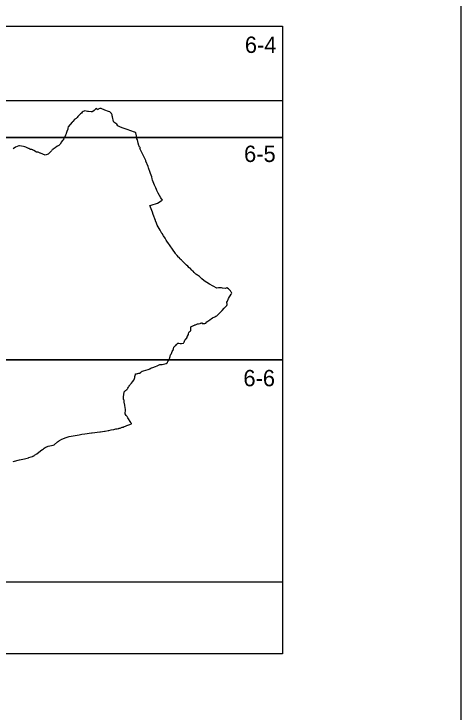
# Model space of a CAD drawing. Extents: x -449577 to -436680, y -1132317 to -1125726.
# Drawn here: x -443787.2 to -443535.8, y -1131954.1 to -1131561.7 of the extents above; entities that cross this region are included whole.
import ezdxf

# ---------------------------------------------------------------- set-up
doc = ezdxf.new("R2010")
doc.units = 0
for name, color, linetype in [('Vrstva 1', 7, 'Continuous'), ('Vrstva 10', 7, 'Continuous'), ('Vrstva 4', 7, 'Continuous')]:
    doc.layers.add(name, color=color, linetype=linetype)

msp = doc.modelspace()

# ---------------------------------------------------------------- linework, layer by layer
at = {"layer": 'Vrstva 1'}
msp.add_lwpolyline([(-445020.82, -1131267.17), (-445020.82, -1132317.17), (-443535.82, -1132317.17), (-443535.82, -1131267.17)], close=True, dxfattribs=at)
msp.add_lwpolyline([(-443787.53, -1131813.29), (-443783.99, -1131812.42), (-443781.22, -1131811.75), (-443780.55, -1131811.54), (-443779.06, -1131811.18), (-443778.85, -1131811.12), (-443777.42, -1131810.73), (-443776.82, -1131810.47), (-443776.6, -1131810.37), (-443776.44, -1131810.31), (-443775.62, -1131809.86), (-443775.56, -1131809.82), (-443774.25, -1131809.04), (-443773.1, -1131807.99), (-443772.45, -1131807.49), (-443772.32, -1131807.38), (-443772.3, -1131807.37), (-443772.14, -1131807.24), (-443771.99, -1131807.14), (-443771.19, -1131806.58), (-443771.13, -1131806.54), (-443771.06, -1131806.49), (-443770.55, -1131806.14), (-443770.18, -1131805.88), (-443769.52, -1131805.42), (-443768.93, -1131805.01), (-443768.77, -1131805.04), (-443768.76, -1131805.04), (-443768.74, -1131805.02), (-443768.01, -1131804.63), (-443765.05, -1131804.05), (-443764.63, -1131803.9), (-443762.6, -1131802.27), (-443762.13, -1131801.93), (-443762.1, -1131801.91), (-443761.74, -1131801.65), (-443761.56, -1131801.53), (-443760.17, -1131800.83), (-443758.76, -1131800.19), (-443758.46, -1131800.04), (-443757.2, -1131799.58), (-443756.2, -1131799.33), (-443750.49, -1131798.27), (-443749.07, -1131798.01), (-443747.36, -1131797.76), (-443743.49, -1131797.19), (-443743.25, -1131797.16), (-443738.95, -1131796.64), (-443738.42, -1131796.58), (-443736.27, -1131796.22), (-443735.95, -1131796.17), (-443734.29, -1131795.9), (-443733.89, -1131795.83), (-443732.48, -1131795.54), (-443731.19, -1131795.27), (-443730.98, -1131795.23), (-443729.81, -1131795), (-443729.14, -1131794.87), (-443729.12, -1131794.87), (-443728.21, -1131794.66), (-443728.14, -1131794.64), (-443727.49, -1131794.48), (-443727.14, -1131794.37), (-443726.25, -1131794.08), (-443725.81, -1131793.93), (-443725.16, -1131793.69), (-443725.04, -1131793.65), (-443723.95, -1131793.16), (-443723.95, -1131793.16), (-443723.83, -1131793.12), (-443723.18, -1131792.89), (-443723.09, -1131792.86), (-443722.66, -1131792.7), (-443721, -1131792.12), (-443721.02, -1131792.07), (-443721.13, -1131791.9), (-443721.29, -1131791.67), (-443721.51, -1131791.35), (-443723.21, -1131788.71), (-443723.42, -1131788.36), (-443723.59, -1131788.09), (-443724.03, -1131787.38), (-443724.56, -1131786.53), (-443724.4, -1131784.17), (-443724.39, -1131784.08), (-443724.78, -1131781.78), (-443724.78, -1131781.76), (-443724.79, -1131781.74), (-443724.79, -1131781.74), (-443724.79, -1131781.71), (-443725.2, -1131779.88), (-443725.21, -1131779.69), (-443725.27, -1131778.89), (-443725.37, -1131778.61), (-443725.38, -1131778.59), (-443725.49, -1131778.37), (-443725.53, -1131778.29), (-443725.54, -1131777.91), (-443725.57, -1131777.21), (-443725.52, -1131776.72), (-443725.52, -1131776.7), (-443725.43, -1131775.84), (-443725.41, -1131775.73), (-443725.12, -1131774.09), (-443725.04, -1131774.01), (-443724.74, -1131773.67), (-443724.68, -1131773.6), (-443724.42, -1131773.48), (-443724.36, -1131773.42), (-443724.1, -1131773.22), (-443723.87, -1131773.04), (-443723.66, -1131772.88), (-443723.6, -1131772.84), (-443723.52, -1131772.71), (-443723.44, -1131772.59), (-443723.33, -1131772.42), (-443723.11, -1131772.09), (-443722.69, -1131771.44), (-443722.56, -1131771.19), (-443722.55, -1131771.18), (-443722.41, -1131770.89), (-443722.36, -1131770.8), (-443722.18, -1131770.47), (-443722.04, -1131770.32), (-443721.74, -1131770.01), (-443721.57, -1131769.83), (-443721.29, -1131769.48), (-443721.16, -1131769.31), (-443720.47, -1131768.46), (-443719.81, -1131767.65), (-443719.52, -1131767.29), (-443719.28, -1131766.12), (-443719.22, -1131765.89), (-443719.15, -1131765.61), (-443718.83, -1131764.3), (-443718.75, -1131764.02), (-443718.75, -1131763.99), (-443718.73, -1131763.94), (-443718.57, -1131763.93), (-443718.55, -1131763.93), (-443718.31, -1131763.93), (-443717.62, -1131763.91), (-443717.61, -1131763.91), (-443717.58, -1131763.91), (-443716.9, -1131763.73), (-443716.7, -1131763.67), (-443716.28, -1131763.56), (-443716.26, -1131763.55), (-443716.2, -1131763.49), (-443715.9, -1131763.21), (-443715.78, -1131763.13), (-443715.44, -1131762.87), (-443715.02, -1131762.55), (-443714.95, -1131762.53), (-443714.39, -1131762.37), (-443711.69, -1131761.61), (-443711.1, -1131761.34), (-443710.77, -1131761.18), (-443710.72, -1131761.16), (-443710.62, -1131761.11), (-443710.26, -1131760.93), (-443710.21, -1131760.91), (-443710.18, -1131760.89), (-443710.17, -1131760.89), (-443710.14, -1131760.87), (-443709.83, -1131760.72), (-443709.77, -1131760.68), (-443709.66, -1131760.63), (-443708.58, -1131760.3), (-443708.15, -1131760.12), (-443707.63, -1131759.9), (-443706.62, -1131759.49), (-443705.2, -1131758.86), (-443705.06, -1131758.85), (-443703.93, -1131758.8), (-443701.53, -1131758.24), (-443701, -1131757.84), (-443700.93, -1131757.72), (-443700.84, -1131757.54), (-443700.58, -1131757.03), (-443700.23, -1131756.6), (-443700.21, -1131756.57), (-443700, -1131756.28), (-443699.89, -1131756.12), (-443699.88, -1131756.11), (-443699.34, -1131754.33), (-443699.33, -1131754.3), (-443699.13, -1131753.35), (-443698.87, -1131752.89), (-443698.68, -1131752.56), (-443698.13, -1131751.44), (-443697.75, -1131750.93), (-443697.72, -1131750.8), (-443697.65, -1131750.5), (-443697.62, -1131750.36), (-443697.56, -1131750.11), (-443697.54, -1131750.01), (-443697.22, -1131749), (-443697.21, -1131748.99), (-443696.92, -1131748.71), (-443696.26, -1131748.08), (-443696.21, -1131748.03), (-443695.74, -1131747.55), (-443695.48, -1131747.29), (-443695.38, -1131747.18), (-443695.01, -1131746.86), (-443694.97, -1131746.86), (-443694.96, -1131746.86), (-443694.55, -1131746.85), (-443694.38, -1131746.86), (-443693.75, -1131746.88), (-443693.04, -1131746.88), (-443692.07, -1131746.79), (-443692.04, -1131746.79), (-443691.79, -1131746.76), (-443691.57, -1131746.4), (-443691.52, -1131746.27), (-443691.5, -1131746.22), (-443691.48, -1131746.16), (-443691.12, -1131745.14), (-443690.98, -1131744.97), (-443690.88, -1131744.86), (-443690.84, -1131744.82), (-443690.78, -1131744.74), (-443690.66, -1131744.61), (-443690.39, -1131744.29), (-443690.3, -1131744.19), (-443690.2, -1131744.07), (-443689.86, -1131743.68), (-443689.79, -1131743.29), (-443689.73, -1131742.98), (-443689.66, -1131742.85), (-443689.11, -1131741.93), (-443689, -1131741.54), (-443688.81, -1131740.84), (-443688.69, -1131740.55), (-443688.4, -1131740.28), (-443687.85, -1131739.77), (-443687.78, -1131739.71), (-443687.68, -1131737.6), (-443686.66, -1131737.11), (-443686.26, -1131736.9), (-443686.01, -1131736.77), (-443685.72, -1131736.61), (-443685.5, -1131736.53), (-443685.16, -1131736.4), (-443685.11, -1131736.39), (-443684.02, -1131735.98), (-443684.01, -1131735.98), (-443683.52, -1131735.92), (-443683.44, -1131735.9), (-443682.41, -1131735.64), (-443682.26, -1131735.6), (-443682.17, -1131735.57), (-443682, -1131735.52), (-443681.47, -1131735.35), (-443681.47, -1131735.35), (-443681.46, -1131735.36), (-443681.46, -1131735.36), (-443681.43, -1131735.42), (-443681.3, -1131735.64), (-443680.42, -1131735.74), (-443680.22, -1131735.76), (-443679.86, -1131735.8), (-443679.77, -1131735.76), (-443679.34, -1131735.58), (-443678.69, -1131734.87), (-443677.05, -1131733.71), (-443676.96, -1131733.64), (-443676.79, -1131733.53), (-443676.28, -1131733.11), (-443675.53, -1131732.51), (-443674.26, -1131731.94), (-443673.64, -1131731.67), (-443673.1, -1131731.43), (-443673.04, -1131731.4), (-443671.39, -1131729.73), (-443670.55, -1131728.84), (-443670.19, -1131728.46), (-443669, -1131727.1), (-443668.4, -1131726.64), (-443668.35, -1131726.6), (-443667.51, -1131725.59), (-443667.31, -1131725.02), (-443667.4, -1131723.69), (-443667.18, -1131723.2), (-443666.54, -1131721.75), (-443665.08, -1131719.27), (-443665.05, -1131719.22), (-443665.05, -1131719.22), (-443665.03, -1131719.19), (-443665, -1131719.15), (-443664.85, -1131718.96), (-443664.59, -1131718.62), (-443664.85, -1131718.32), (-443664.99, -1131718.1), (-443665.46, -1131717.36), (-443665.66, -1131717.17), (-443665.81, -1131717.01), (-443666, -1131716.81), (-443666.58, -1131716.24), (-443667.43, -1131715.77), (-443667.88, -1131715.95), (-443668.21, -1131716.07), (-443669.96, -1131715.8), (-443670.57, -1131715.71), (-443670.71, -1131715.7), (-443671.3, -1131715.68), (-443671.68, -1131715.63), (-443671.84, -1131715.6), (-443671.88, -1131715.6), (-443671.91, -1131715.59), (-443671.91, -1131715.59), (-443671.94, -1131715.6), (-443672.04, -1131715.63), (-443672.17, -1131715.66), (-443673.07, -1131715.9), (-443673.14, -1131715.87), (-443675.21, -1131714.83), (-443677.23, -1131713.55), (-443680.14, -1131711.73), (-443680.3, -1131711.59), (-443680.34, -1131711.56), (-443680.43, -1131711.48), (-443681.57, -1131710.55), (-443682.72, -1131709.5), (-443682.83, -1131709.4), (-443684.04, -1131708.64), (-443684.32, -1131708.41), (-443684.95, -1131707.91), (-443685.26, -1131707.67), (-443685.76, -1131707.14), (-443686.48, -1131706.38), (-443686.63, -1131706.22), (-443687.09, -1131705.73), (-443688.06, -1131704.7), (-443688.26, -1131704.59), (-443688.26, -1131704.59), (-443688.44, -1131704.5), (-443688.64, -1131704.4), (-443689.47, -1131703.57), (-443690.1, -1131702.94), (-443691.28, -1131701.77), (-443692.21, -1131700.83), (-443692.37, -1131700.68), (-443692.81, -1131700.23), (-443693.05, -1131699.99), (-443693.14, -1131699.9), (-443693.18, -1131699.86), (-443693.7, -1131699.34), (-443694.34, -1131698.69), (-443694.42, -1131698.61), (-443694.44, -1131698.59), (-443694.59, -1131698.44), (-443695.42, -1131697.6), (-443695.8, -1131697.1), (-443696.08, -1131696.73), (-443696.4, -1131696.3), (-443696.76, -1131695.82), (-443697.71, -1131694.56), (-443698.08, -1131694.02), (-443700.62, -1131690.28), (-443700.79, -1131690.02), (-443701.56, -1131688.83), (-443702.23, -1131687.82), (-443703.07, -1131686.49), (-443703.87, -1131685.22), (-443703.95, -1131685.09), (-443705.04, -1131683.24), (-443706.72, -1131680.39), (-443706.72, -1131680.38), (-443706.72, -1131680.38), (-443706.73, -1131680.38), (-443707.06, -1131679.4), (-443707.51, -1131678.1), (-443707.57, -1131677.9), (-443708.95, -1131674.39), (-443709.24, -1131673.14), (-443710.72, -1131669.46), (-443710.09, -1131669.26), (-443706.37, -1131668.02), (-443704.4, -1131666.8), (-443704.22, -1131666.69), (-443704.16, -1131666.65), (-443703.96, -1131666.53), (-443703.69, -1131666.36), (-443704.61, -1131665.17), (-443706.02, -1131662.39), (-443706.77, -1131660.92), (-443707.3, -1131659.76), (-443707.32, -1131659.72), (-443707.38, -1131659.59), (-443707.39, -1131659.56), (-443707.41, -1131659.53), (-443707.45, -1131659.44), (-443707.78, -1131658.71), (-443708.1, -1131657.92), (-443708.81, -1131656.15), (-443709.22, -1131655.11), (-443709.37, -1131654.48), (-443709.63, -1131653.35), (-443710.37, -1131651.46), (-443710.57, -1131650.86), (-443711.51, -1131648.23), (-443711.78, -1131647.51), (-443712.97, -1131644.42), (-443713.04, -1131644.24), (-443713.07, -1131644.16), (-443716.42, -1131637.35), (-443716.11, -1131637.21), (-443716.09, -1131637.2), (-443716.19, -1131637.03), (-443716.27, -1131636.93), (-443716.44, -1131636.7), (-443716.5, -1131636.62), (-443717.11, -1131635.14), (-443717.16, -1131634.85), (-443717.26, -1131634.39), (-443717.27, -1131634.33), (-443717.78, -1131632.49), (-443718.08, -1131631.86), (-443718.09, -1131631.78), (-443718.13, -1131631.42), (-443718.27, -1131630.33), (-443718.55, -1131628.49), (-443718.61, -1131628.47), (-443718.91, -1131628.37), (-443719.29, -1131628.11), (-443719.3, -1131628.11), (-443723.6, -1131626.7), (-443726.39, -1131625.72), (-443727.7, -1131625.1), (-443728.67, -1131624.54), (-443729.39, -1131623.76), (-443731.07, -1131622.49), (-443731.13, -1131622.19), (-443731.71, -1131619.49), (-443731.86, -1131618.95), (-443732.04, -1131618.44), (-443732.09, -1131618.28), (-443732.34, -1131617.76), (-443732.59, -1131617.45), (-443733.17, -1131616.76), (-443733.92, -1131616.55), (-443736.1, -1131615.89), (-443738.19, -1131614.93), (-443738.81, -1131614.93), (-443739.76, -1131615.3), (-443739.89, -1131615.39), (-443739.96, -1131615.44), (-443740.1, -1131615.54), (-443740.14, -1131615.57), (-443740.16, -1131615.55), (-443740.37, -1131615.3), (-443740.62, -1131615.02), (-443740.7, -1131614.92), (-443740.79, -1131614.96), (-443741.3, -1131615.35), (-443741.49, -1131615.5), (-443742.16, -1131616.02), (-443742.91, -1131616.58), (-443743.25, -1131616.8), (-443743.84, -1131616.76), (-443745.32, -1131616.61), (-443745.78, -1131616.52), (-443747.37, -1131616.2), (-443747.67, -1131616.31), (-443748.23, -1131616.66), (-443748.78, -1131616.98), (-443749.27, -1131617.44), (-443749.8, -1131617.93), (-443750.2, -1131618.32), (-443750.21, -1131618.33), (-443750.54, -1131618.67), (-443750.67, -1131618.81), (-443751.18, -1131619.36), (-443751.63, -1131619.91), (-443751.79, -1131620.1), (-443752.15, -1131620.53), (-443752.89, -1131620.86), (-443752.91, -1131620.86), (-443753.11, -1131621.11), (-443753.97, -1131622.13), (-443754.35, -1131622.58), (-443755.48, -1131623.94), (-443755.49, -1131623.95), (-443756.73, -1131625.12), (-443756.85, -1131625.96), (-443756.9, -1131626.33), (-443756.94, -1131626.43), (-443757.42, -1131627.78), (-443757.86, -1131629.02), (-443757.89, -1131629.1), (-443758.19, -1131629.79), (-443759.12, -1131631.97), (-443759.14, -1131631.98), (-443759.71, -1131632.66), (-443760.01, -1131633.01), (-443760.01, -1131633.02), (-443760.35, -1131633.56), (-443761.22, -1131634.95), (-443761.31, -1131635.09), (-443761.48, -1131635.22), (-443762.01, -1131635.61), (-443762.62, -1131636.06), (-443762.62, -1131636.06), (-443763.59, -1131636.69), (-443763.72, -1131636.78), (-443763.9, -1131636.9), (-443765.2, -1131637.76), (-443765.21, -1131637.77), (-443765.47, -1131638.03), (-443765.59, -1131638.15), (-443765.81, -1131638.38), (-443766.09, -1131638.66), (-443766.66, -1131639.23), (-443767.82, -1131640.39), (-443768.02, -1131640.47), (-443769.52, -1131641.04), (-443772.33, -1131639.92), (-443772.33, -1131639.93), (-443772.34, -1131639.95), (-443773.25, -1131639.57), (-443773.56, -1131639.44), (-443773.58, -1131639.44), (-443773.97, -1131639.44), (-443774.45, -1131639.44), (-443776.01, -1131638.45), (-443776.27, -1131638.32), (-443776.56, -1131638.16), (-443776.62, -1131638.13), (-443776.66, -1131638.11), (-443777.2, -1131637.88), (-443777.25, -1131637.88), (-443777.26, -1131637.88), (-443777.41, -1131637.87), (-443777.53, -1131637.86), (-443777.84, -1131637.84), (-443777.86, -1131637.84), (-443777.86, -1131637.84), (-443777.97, -1131637.8), (-443778.21, -1131637.7), (-443778.81, -1131637.45), (-443778.97, -1131637.38), (-443780.49, -1131636.65), (-443781.11, -1131636.47), (-443781.78, -1131636.27), (-443784.1, -1131635.84), (-443784.11, -1131635.84), (-443784.51, -1131635.95), (-443786.25, -1131636.53), (-443786.38, -1131636.64), (-443787.59, -1131637.6)], dxfattribs=at)
at = {"layer": 'Vrstva 10'}
msp.add_lwpolyline([(-443636.23, -1131610.43), (-443636.23, -1131921.41), (-443969.1, -1131921.41), (-443969.1, -1131756.11), (-443948.73, -1131756.11), (-443948.73, -1131631.11), (-443948.73, -1131610.43), (-443636.23, -1131610.43)], dxfattribs=at)
at = {"layer": 'Vrstva 4'}
msp.add_line((-443948.73, -1131568.61), (-443636.23, -1131568.61), dxfattribs=at)
msp.add_lwpolyline([(-443636.23, -1131568.61), (-443636.23, -1131631.11), (-443792.48, -1131631.11), (-443792.48, -1131568.61)], dxfattribs=at)
for points in [[(-443636.23, -1131631.11), (-443636.23, -1131756.11), (-443792.48, -1131756.11), (-443792.48, -1131631.11)], [(-443636.23, -1131756.11), (-443636.23, -1131881.11), (-443792.48, -1131881.11), (-443792.48, -1131756.11)]]:
    msp.add_lwpolyline(points, close=True, dxfattribs=at)

# ---------------------------------------------------------------- texts
at = {"layer": 'Vrstva 1'}
for s, p in [('6-4', (-443657.36, -1131583.66)), ('6-5', (-443657.81, -1131644.95)), ('6-6', (-443658.18, -1131771.02))]:
    msp.add_text(s, height=9.2, dxfattribs=at).set_placement(p)

doc.saveas('drawing.dxf')
